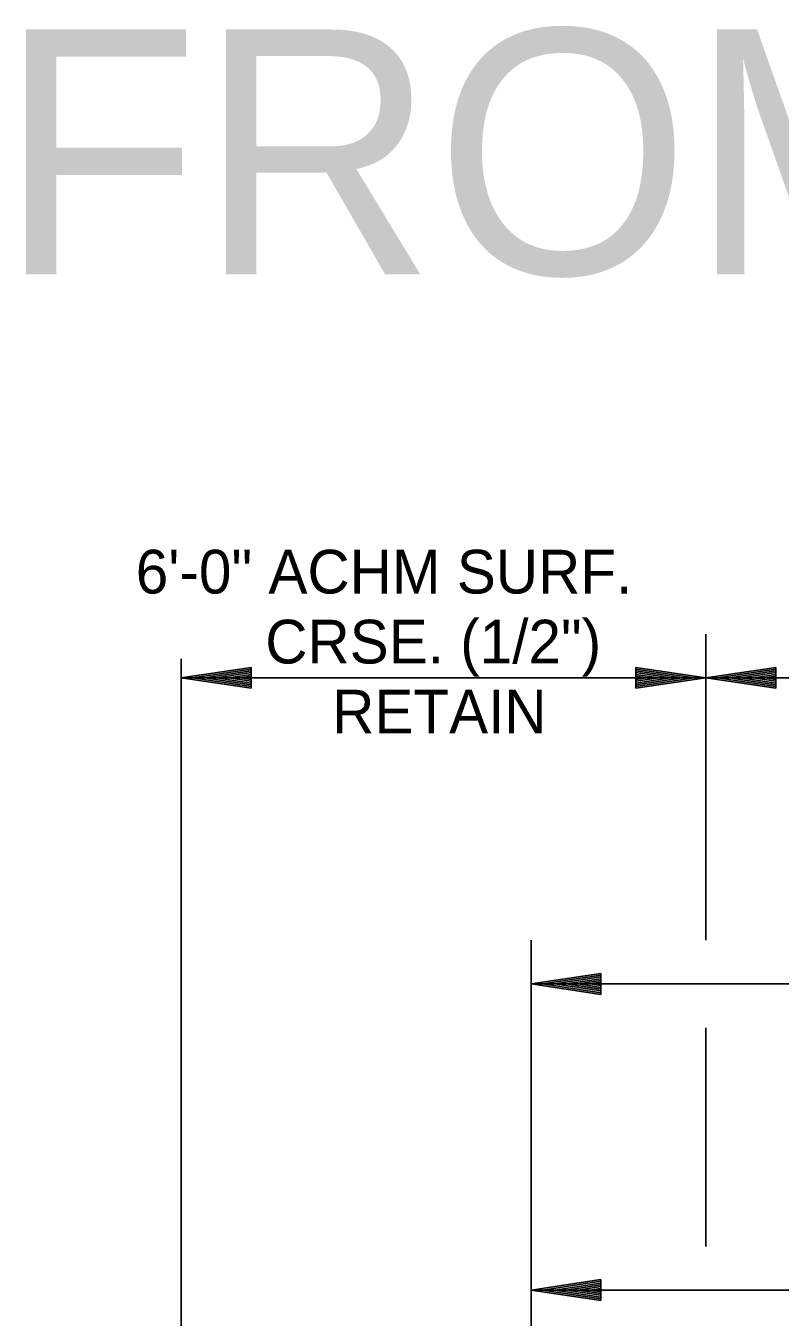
# Model space of a CAD drawing. Extents: x 60325 to 61047, y 53669 to 53767.
# Drawn here: x 60345.47 to 60354.1, y 53701.21 to 53715.97 of the extents above; entities that cross this region are included whole.
import ezdxf

# ---------------------------------------------------------------- set-up
doc = ezdxf.new("R2010")
doc.units = 0
doc.layers.add('Level 63', color=7, linetype='Continuous')
doc.layers.add('R_Border Prem', color=7, linetype='Continuous')

msp = doc.modelspace()

# ---------------------------------------------------------------- linework, layer by layer
at = {"layer": 'R_Border Prem'}
for p, q in [((60353.247, 53705.515), (60353.247, 53709.015)), ((60347.247, 53696.011), (60347.247, 53708.733)), ((60348.047, 53708.635), (60347.247, 53708.515)), ((60348.047, 53708.395), (60348.047, 53708.635)), ((60352.447, 53708.635), (60353.247, 53708.515)), ((60352.447, 53708.635), (60352.447, 53708.395)), ((60354.047, 53708.635), (60353.247, 53708.515)), ((60354.047, 53708.395), (60354.047, 53708.635)), ((60347.247, 53708.515), (60353.247, 53708.515)), ((60348.047, 53708.395), (60347.247, 53708.515)), ((60348.047, 53708.615), (60347.38, 53708.515)), ((60348.047, 53708.415), (60347.38, 53708.515)), ((60348.047, 53708.595), (60347.518, 53708.515)), ((60348.047, 53708.435), (60347.518, 53708.515)), ((60348.047, 53708.575), (60347.651, 53708.515)), ((60348.047, 53708.455), (60347.651, 53708.515)), ((60348.047, 53708.554), (60347.787, 53708.515)), ((60348.047, 53708.476), (60347.787, 53708.515)), ((60348.047, 53708.534), (60347.92, 53708.515)), ((60348.047, 53708.496), (60347.92, 53708.515)), ((60352.447, 53708.615), (60353.113, 53708.515)), ((60352.447, 53708.595), (60352.975, 53708.515)), ((60352.447, 53708.575), (60352.842, 53708.515)), ((60352.447, 53708.554), (60352.707, 53708.515)), ((60352.447, 53708.534), (60352.573, 53708.515)), ((60352.447, 53708.395), (60353.247, 53708.515)), ((60352.447, 53708.476), (60352.707, 53708.515)), ((60352.447, 53708.435), (60352.975, 53708.515)), ((60352.447, 53708.415), (60353.113, 53708.515)), ((60352.447, 53708.455), (60352.842, 53708.515)), ((60352.447, 53708.496), (60352.573, 53708.515)), ((60381.247, 53708.515), (60353.247, 53708.515)), ((60354.047, 53708.395), (60353.247, 53708.515)), ((60354.047, 53708.615), (60353.38, 53708.515)), ((60354.047, 53708.415), (60353.38, 53708.515)), ((60354.047, 53708.595), (60353.518, 53708.515)), ((60354.047, 53708.435), (60353.518, 53708.515)), ((60354.047, 53708.575), (60353.651, 53708.515)), ((60354.047, 53708.455), (60353.651, 53708.515)), ((60354.047, 53708.554), (60353.787, 53708.515)), ((60354.047, 53708.476), (60353.787, 53708.515)), ((60354.047, 53708.534), (60353.92, 53708.515)), ((60354.047, 53708.496), (60353.92, 53708.515)), ((60351.247, 53695.511), (60351.247, 53705.515)), ((60352.047, 53705.135), (60351.247, 53705.015)), ((60352.047, 53705.115), (60351.38, 53705.015)), ((60352.047, 53705.095), (60351.518, 53705.015)), ((60352.047, 53705.075), (60351.651, 53705.015)), ((60352.047, 53704.895), (60352.047, 53705.135)), ((60383.247, 53705.015), (60351.247, 53705.015)), ((60352.047, 53704.895), (60351.247, 53705.015)), ((60352.047, 53704.915), (60351.38, 53705.015)), ((60352.047, 53704.935), (60351.518, 53705.015)), ((60352.047, 53704.955), (60351.651, 53705.015)), ((60352.047, 53705.054), (60351.787, 53705.015)), ((60352.047, 53704.976), (60351.787, 53705.015)), ((60352.047, 53705.034), (60351.92, 53705.015)), ((60352.047, 53704.996), (60351.92, 53705.015)), ((60353.247, 53702.013), (60353.247, 53704.515)), ((60352.047, 53701.635), (60351.247, 53701.515)), ((60352.047, 53701.615), (60351.38, 53701.515)), ((60352.047, 53701.595), (60351.518, 53701.515)), ((60352.047, 53701.575), (60351.651, 53701.515)), ((60352.047, 53701.554), (60351.787, 53701.515)), ((60352.047, 53701.534), (60351.92, 53701.515)), ((60352.047, 53701.395), (60352.047, 53701.635)), ((60383.247, 53701.515), (60351.247, 53701.515)), ((60352.047, 53701.395), (60351.247, 53701.515)), ((60352.047, 53701.415), (60351.38, 53701.515)), ((60352.047, 53701.435), (60351.518, 53701.515)), ((60352.047, 53701.455), (60351.651, 53701.515)), ((60352.047, 53701.476), (60351.787, 53701.515)), ((60352.047, 53701.496), (60351.92, 53701.515))]:
    msp.add_line(p, q, dxfattribs=at)

# ---------------------------------------------------------------- texts
at = {"layer": 'Level 63'}
msp.add_text('FROM 090292 PLANS', height=2.8, dxfattribs=at).set_placement((60345.163, 53713.128))
at = {"layer": 'R_Border Prem'}
for s, p in [('6\'-0" ACHM SURF.', (60346.727, 53709.479)), ('CRSE. (1/2")', (60348.208, 53708.679)), ('RETAIN', (60348.973, 53707.879))]:
    msp.add_text(s, height=0.5, dxfattribs=at).set_placement(p)

doc.saveas('drawing.dxf')
